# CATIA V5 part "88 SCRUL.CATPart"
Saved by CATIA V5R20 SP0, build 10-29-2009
Part number: 88 SCRUL
Definition: NONE
Nomenclature: 88 SCRUL
Source: Unknown
Description: PART-88 SCRUL-DESC
Bounding box of the stored display mesh (mm): x 0 to 750, y -6 to 2.304, z -17.5 to 17.5
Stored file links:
  C:\Users\Raffaele\Desktop\3D X SITO CF\88 SCRUL\GSB_OILLESS_M3100335750\88 SCRUL.CATPart
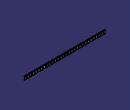
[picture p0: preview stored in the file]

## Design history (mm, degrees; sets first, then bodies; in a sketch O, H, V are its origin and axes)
Body1 "88 SCRUL" (main body)
  Solid1: solid without history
